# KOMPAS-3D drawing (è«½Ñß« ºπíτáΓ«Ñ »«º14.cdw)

Views: Вид 1
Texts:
  Колесо зубчатое
  Noncommercial version
  Модуль
  Число зубьев
  Угол наклона
  Symbol type B
  Нормальный исходный контур
  ГОСТ 13755-81
  Коэффициент смещения
  Средняя длина общей нормали
  Делительный диаметр
  Высота зуба
  Обозначение чертежа сопряженного зубчатого колеса
  Ra3.2
  Ra6.3
  1. H14, h14,    IT14 2 .
  2. Неуказанные радиусы R 6.
  3. Неуказанные предельные отклонения размеров полученных литьем по
  классу ГОСТ 2009-55.
  4. Формовочные уклоны тип   ГОСТ 3212-57.
  Сталь 55Л ГОСТ 977-88
  ДГТУ
Dimensions and other numbers on the sheet: 5; 82; 0; 204,356; 574,00; 15,75; 000.11; 588,5; 136,4; 32; 360; 6 отв.; 120; 72; 110; 6 фасок; 200; 2 фаски; 2,5; 520; 10; 125; 52; 26; 0,05; 0,002; 0,008; 1:4; 1; 0,75; 2; 3; 4; 6; 7; 8; 9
